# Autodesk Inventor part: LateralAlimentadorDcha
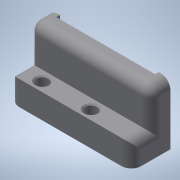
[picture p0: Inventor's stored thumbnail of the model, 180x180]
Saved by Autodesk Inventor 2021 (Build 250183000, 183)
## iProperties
Created: 2021-02
Part Number: LateralAlimentadorDcha
Material: Genérico
Document SubType Name: Modeling
Designer: ATOUZA
Density: 1 g/cm^3
Appearance: Valor por defecto
Author: ATOUZA
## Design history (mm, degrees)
node "Plano de trabajo1"
sketch "Boceto1"
  geometry: L1 (25, 26)-(-25, 26); L2 (-25, 26)-(-25, 18); L3 (-25, 18)-(-20.25, 18); L4 (-20.25, 18)-(-20.25, 19.5); L5 (25, 26)-(25, 18); L6 (25, 18)-(20.25, 18); L7 (20.25, 18)-(20.25, 19.5); L8 (25, 26)-(-25, 26); L9 (-20.25, 19.5)-(20.25, 19.5); 1 further point
  constraints: 18 end point, 3 parallel, 2 horizontal, 2 perpendicular, 1 point on line
  dimensions: "d2" = 4.75 distance of L5.end L6.end; "d3" = 8 distance of L1.start L5.end; "d4" = 50 distance of L1.start L1.end; "d38" = 40.5 distance of L4.end L7.end; "d39" = 1.5 distance of L6.end L7.end; "d40" = 4.75 distance of L2.end L3.end
extrude "Extrusión2" new body sketch "Boceto1" distance "d17" = 25; taper "d18" = 0 deg
sketch "Boceto4"
  geometry: L1 (-25, 26)-(25, 26) reference; L2 (25, 26)-(-25, 26); L3 (-25, 26)-(-25, 34); L4 (-25, 34)-(25, 34); L5 (25, 34)-(25, 26); L6 (-20.25, 18)-(-20.25, 19.5) reference; L7 (-20.25, 19.5)-(19.75, 19.5); L8 (19.75, 19.5)-(19.75, -20.5); L9 (19.75, -20.5)-(-20.25, -20.5); L10 (-20.25, -20.5)-(-20.25, 19.5); L11 (0, 0)-(0, 30); L12 (0, 30)-(-25, 30); L13 (0, 30)-(25, 30); C1 r 2 at (-12.5, 30); C2 r 2 at (12.5, 30); 1 further point
  constraints: 22 end point, 4 midpoint, 4 parallel, 2 centre point, 2 horizontal, 2 perpendicular, 1 vertical
  dimensions: "d19" = 8 distance of L2.end L3.end; "d22" = 40 distance of L8.end L9.end; "d23" = 40 distance of L7.end L8.end; "d26" = 30 distance of L11.start L11.end; "d27" = 4 diameter of C1; "d28" = 4 diameter of C2
extrude "Extrusión3" join sketch "Boceto4" distance "d20" = 10; taper "d21" = 0 deg
sketch "Boceto5"
  geometry: L1 (-25, -34)-(25, -34) reference; L2 (-25, -26)-(25, -26) reference; L3 (0, -30)-(-31, -30); L4 (0, -30)-(25, -30); L5 (25, -18)-(25, -34) reference; L6 (4.811, 50.86)-(5.011, 50.86) reference; L7 (-15.5, 429.14)-(-15.5, -50.86) reference; L8 (4.5, 429.14)-(4.5, -50.86) reference; 3 further points
  constraints: 4 end point, 4 point on line, 1 horizontal, 1 midpoint
hole "Agujero2" sketch "Boceto5" diameter "d29" = 5; stored, may be unused: countersink angle "d33" = 90 deg, drill point angle "d35" = 118 deg; dims "d30" = 6, "d31" = 6, "d32" = 2, "d34" = 8
fillet "Empalme1" dims "d37" = 4
node "Sólido2"
node "Referencia3"
node "Referencia4"
node "Referencia5"
